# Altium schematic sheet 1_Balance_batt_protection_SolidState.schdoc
size 431 x 309 mm; Symbol: Sheet-Symbol_A3; Device: Sheet-Symbol_A3; @Project Name: BFMC_Power Board V2; @Page Count: 5; @Update Date: 2024-08-30; @Create Date: 2024-08-30; @Schematic Name: Balance_batt_protection_SolidState_4; @Page No: 1; @Page Name: Balance_batt_protection_SolidState; Company: EasyEDA.com; Reviewed: EasyEDA; Version: V0.1; Page Size: A3; Part Number: JLCPCB-001; Drawn: EasyEDA; @Board Name: greater0603 Csample-3V3config; @Create Time: 12:44:13; @Update Time: 13:32:06
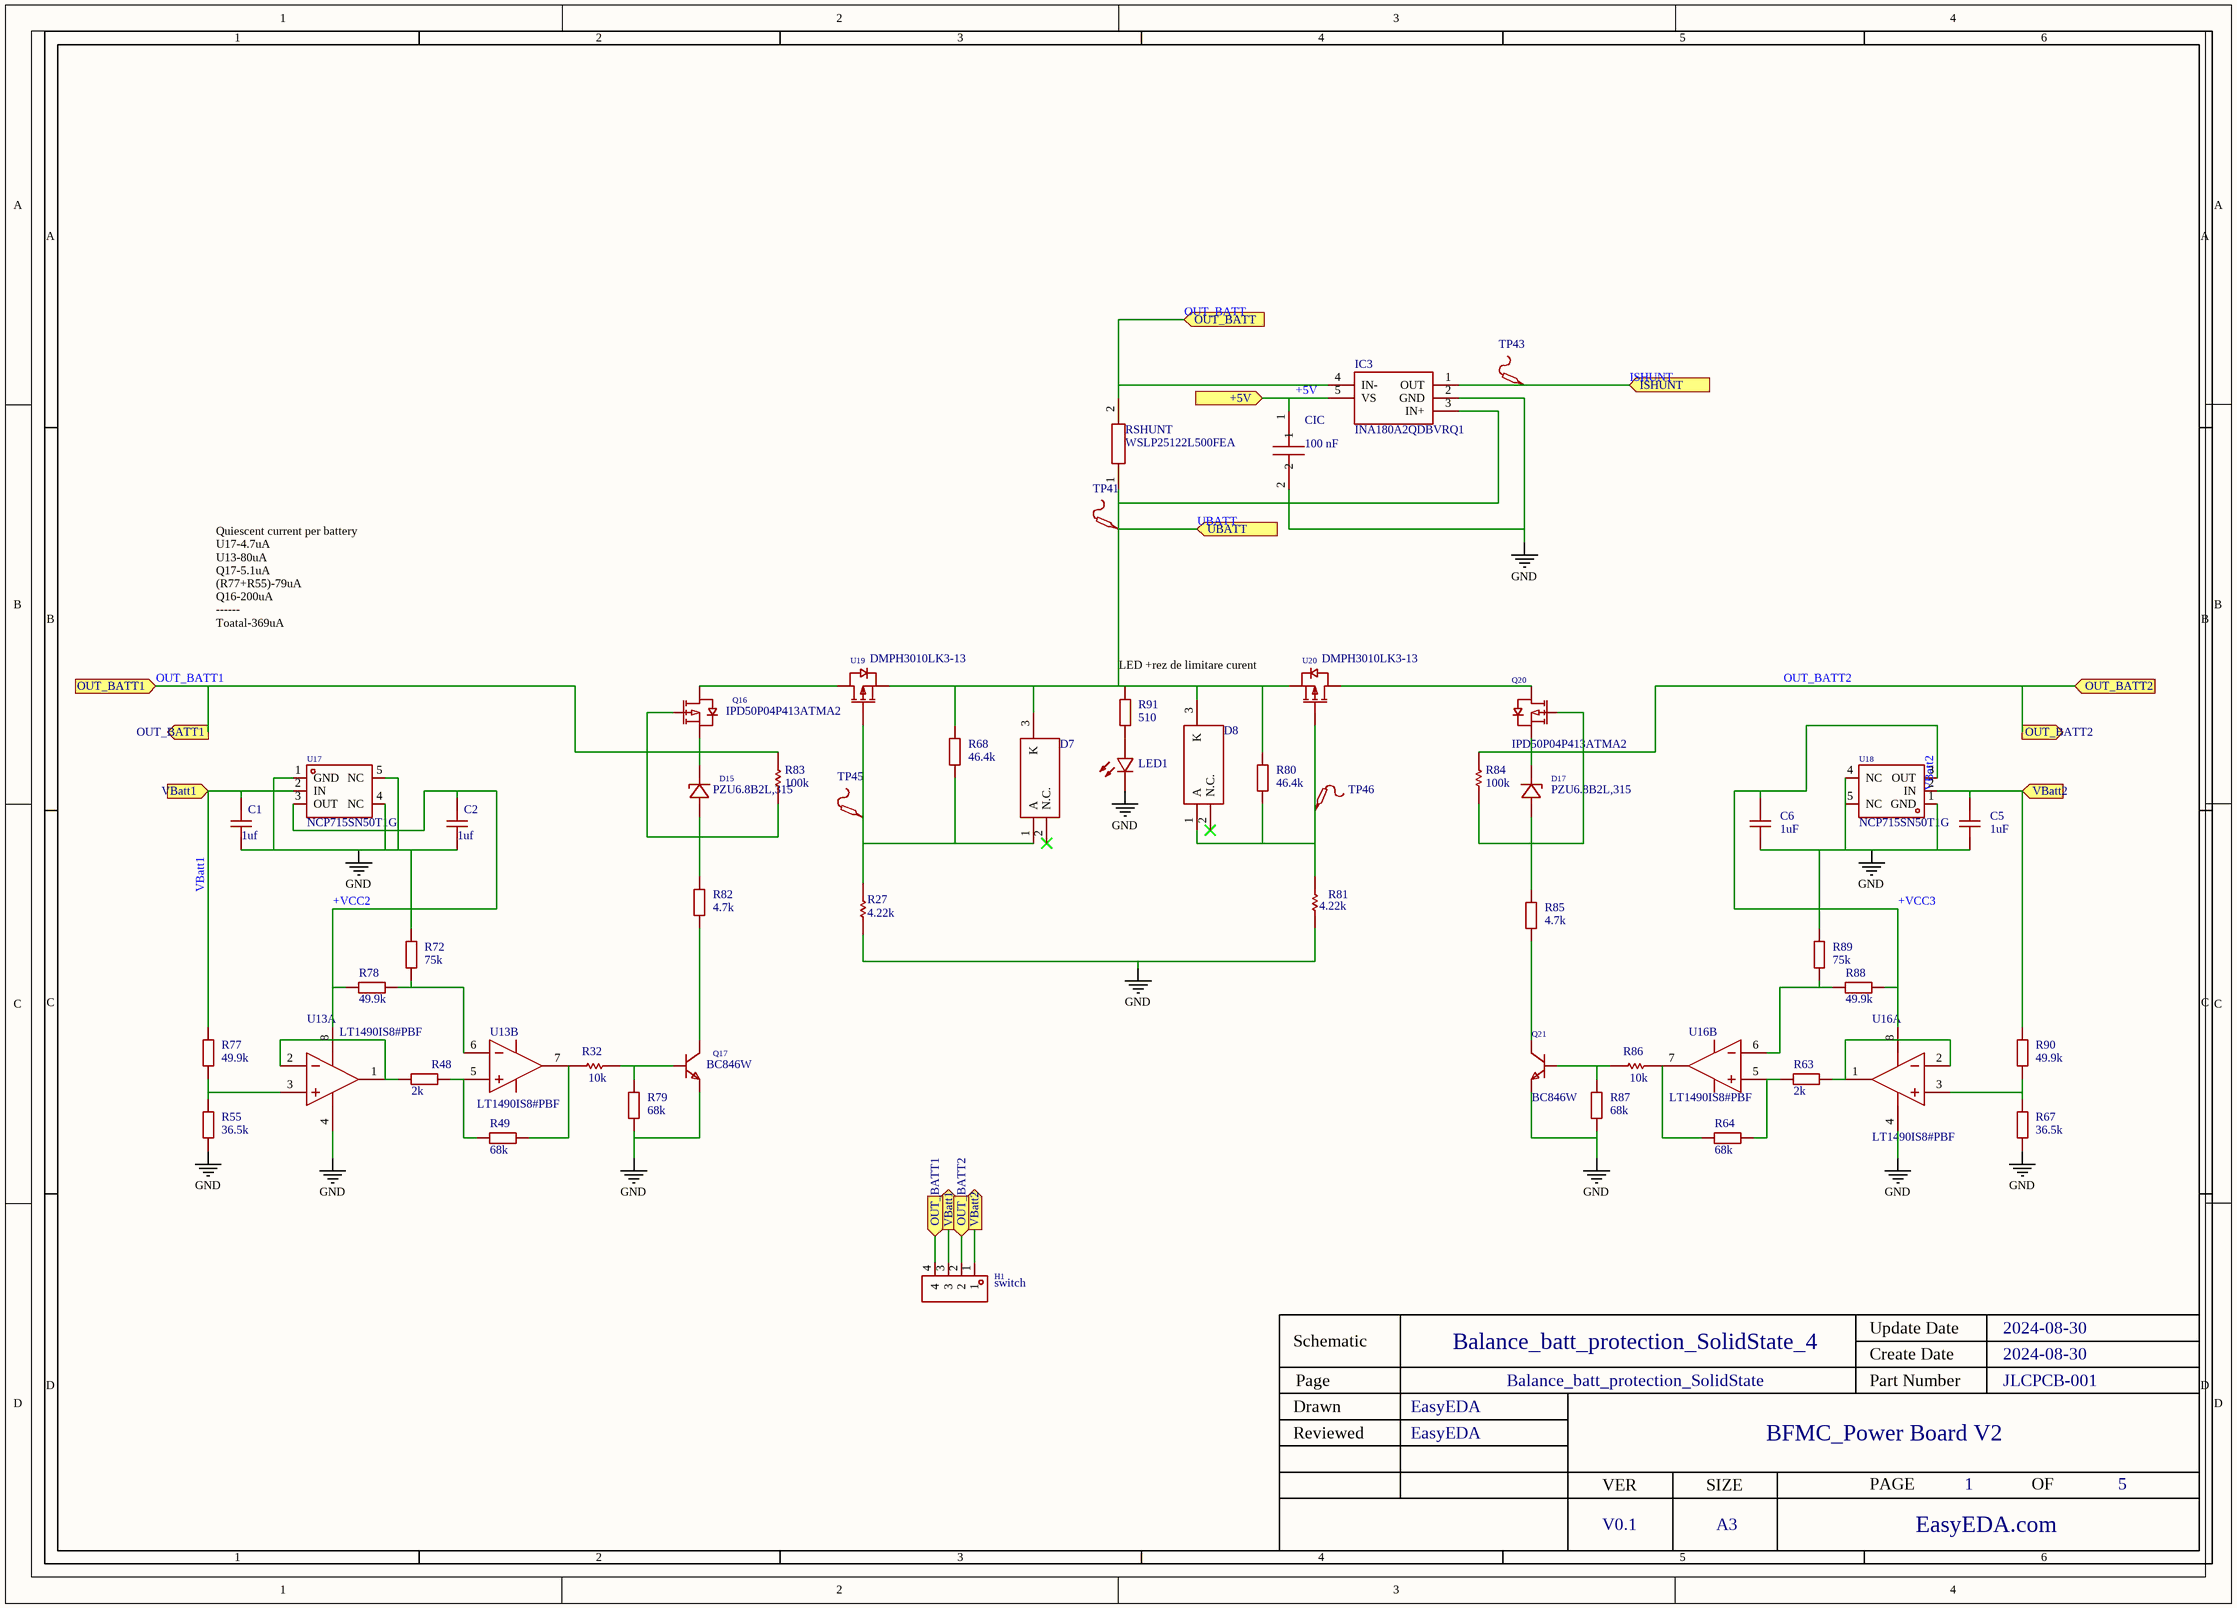
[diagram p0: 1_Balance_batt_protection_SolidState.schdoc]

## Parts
C1  1uf  [C9]  (value not drawn)
C2  1uf  [C9]  (value not drawn)
C5  1uF  [C9]  (value not drawn)
C6  1uF  [C9]  (value not drawn)
CIC  value 100 nF  [Cbst2]  (hidden comment: C2012X7S1C106K)
D7  SZBZX84C18ET1G  [SZBZX84C18ET1G]  (value not drawn)
D8  SZBZX84C18ET1G  [SZBZX84C18ET1G]  (value not drawn)
D15  PZU6.8B2L,315  [DFN1006-2L-RD]  (value not drawn)
D17  PZU6.8B2L,315  [DFN1006-2L-RD]  (value not drawn)
H1  switch  [M2021BB1W01]  (value not drawn)
IC3  INA180A2QDBVRQ1  [INA180A2QDBVRQ1]  (value not drawn)
LED1  ASCKCG00-NW5X5020302  [LEDGREEN]  (value not drawn)
Q16  IPD50P04P413ATMA2  [PG-TO252-3_L6.3-W6.5-P4.57-LS10.0-BR-CW]  (value not drawn)
Q17  BC846W  [SOT-323-3_L2.2-W1.3-P1.30-LS2.2-BR]  (value not drawn)
Q20  IPD50P04P413ATMA2  [PG-TO252-3_L6.3-W6.5-P4.57-LS10.0-BR-CW]  (value not drawn)
Q21  BC846W  [SOT-323-3_L2.2-W1.3-P1.30-LS2.2-BR]  (value not drawn)
R27  value 4.22k  [R0805_NEW]  (hidden comment: MCR03..PFX1002)
R32  value 10k  [R0603]  (hidden comment: MCR03..PFX1002)
R48  2k  [R35]  (value not drawn)
R49  68k  [R0603]  (value not drawn)
R55  36.5k  [R0603]  (value not drawn)
R63  2k  [R35]  (value not drawn)
R64  68k  [R0603]  (value not drawn)
R67  36.5k  [R0603]  (value not drawn)
R68  46.4k  [R0603]  (value not drawn)
R72  75k  [R0603]  (value not drawn)
R77  49.9k  [R0603]  (value not drawn)
R78  49.9k  [R0603]  (value not drawn)
R79  68k  [R0603]  (value not drawn)
R80  46.4k  [R0603]  (value not drawn)
R81  value 4.22k  [R0805_NEW]  (hidden comment: MCR03..PFX1002)
R82  4.7k  [R0603]  (value not drawn)
R83  value 100k  [R0805_NEW]  (hidden comment: MCR03..PFX1002)
R84  value 100k  [R0805_NEW]  (hidden comment: MCR03..PFX1002)
R85  4.7k  [R0603]  (value not drawn)
R86  value 10k  [R0603]  (hidden comment: MCR03..PFX1002)
R87  68k  [R0603]  (value not drawn)
R88  49.9k  [R0603]  (value not drawn)
R89  75k  [R0603]  (value not drawn)
R90  49.9k  [R0603]  (value not drawn)
R91  510  [R0805_NEW]  (value not drawn)
RSHUNT  WSLP25122L500FEA  [WSLP25122L000FEA BUN]  (value not drawn)
TP41  Test-Point  [Test-Point-0.5mm]  (value not drawn)
TP43  Test-Point  [Test-Point-0.5mm]  (value not drawn)
TP45  Test-Point  [Test-Point-0.5mm]  (value not drawn)
TP46  Test-Point  [Test-Point-0.5mm]  (value not drawn)
U13  LT1490IS8#PBF  [SO-8_L4.9-W3.9-P1.27-LS5.9-BL]  (value not drawn)  (parts A,B of 2)
U16  LT1490IS8#PBF  [SO-8_L4.9-W3.9-P1.27-LS5.9-BL]  (value not drawn)  (parts A,B of 2)
U17  NCP715SN50T1G  [TSOP-5_L3.0-W1.5-P0.95-BL]  (value not drawn)
U18  NCP715SN50T1G  [TSOP-5_L3.0-W1.5-P0.95-BL]  (value not drawn)
U19  DMPH3010LK3-13  [PG-TO252-3_L6.3-W6.5-P4.57-LS10.0-BR-CW]  (value not drawn)
U20  DMPH3010LK3-13  [PG-TO252-3_L6.3-W6.5-P4.57-LS10.0-BR-CW]  (value not drawn)

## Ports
+5V (in), ISHUNT (in), OUT_BATT1 (in), OUT_BATT1 (out), OUT_BATT2 (in), OUT_BATT2 (out), OUT_BATT (in), UBATT (in), VBatt1 (in), VBatt1 (out), VBatt2 (in), VBatt2 (out)

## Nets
GND: C1.2 C2.2 C5.2 C6.2 CIC.2 IC3.2(GND) LED1.1(C) Q17.2(E) Q21.2(E) R27.2 R55.1 R67.1 R72.2 R79.1 R81.2 R87.1 R89.2 U13.4(V-) U16.4(V-) U17.1(GND) U17.4(NC) U17.5(NC) U18.1(GND) U18.4(NC) U18.5(NC)
+5V: CIC.1 IC3.5(VS) ; port +5V
+VCC2: C2.1 R78.2 U13.8(V+) U17.3(OUT)
+VCC3: C6.1 R88.1 U16.8(V+) U18.3(OUT)
ISHUNT: IC3.1(OUT) TP43.1 ; port ISHUNT
OUT_BATT: IC3.4(IN-) RSHUNT.2 ; port OUT_BATT
OUT_BATT1: D15.1(C) H1.4 Q16.3(S) R83.2 ; port OUT_BATT1
OUT_BATT2: D17.1(C) H1.2 Q20.3(S) R84.2 ; port OUT_BATT2
UBATT: D7.3(K) D8.3(K) IC3.3(IN+) R68.2 R80.2 R91.2 RSHUNT.1 TP41.1 U19.3(S) U20.3(S) ; port UBATT
VBatt1: C1.1 H1.3 R77.2 U17.2(IN) ; port VBatt1
VBatt2: C5.1 H1.1 R90.1 U18.2(IN) ; port VBatt2
NetD7_1: D7.1(A) R27.1 R68.1 TP45.1 U19.1(G)
NetD8_1: D8.1(A) R80.1 R81.1 TP46.1 U20.1(G)
NetD15_2: D15.2(A) Q16.1(G) R82.2 R83.1
NetD17_2: D17.2(A) Q20.1(G) R84.1 R85.2
NetLED1_2: LED1.2(A) R91.1
NetQ16_2: Q16.2(D) U19.2(D)
NetQ17_1: Q17.1(B) R32.2 R79.2
NetQ17_3: Q17.3(C) R82.1
NetQ20_2: Q20.2(D) U20.2(D)
NetQ21_1: Q21.1(B) R86.1 R87.2
NetQ21_3: Q21.3(C) R85.1
NetR32_1: R32.1 R49.2 U13.7(OUT_B)
NetR48_1: R48.1 U13.1(OUT) U13.2(-IN)
NetR48_2: R48.2 R49.1 U13.5(+IN_B)
NetR55_2: R55.2 R77.1 U13.3(+IN)
NetR63_1: R63.1 U16.1(OUT) U16.2(-IN)
NetR63_2: R63.2 R64.1 U16.5(+IN_B)
NetR64_2: R64.2 R86.2 U16.7(OUT_B)
NetR67_2: R67.2 R90.2 U16.3(+IN)
NetR72_1: R72.1 R78.1 U13.6(-IN_B)
NetR88_2: R88.2 R89.1 U16.6(-IN_B)

Not connected (* = marked no-connect by the designer): D7 2(N.C.)*; D8 2(N.C.)*

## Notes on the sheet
- Quiescent current per battery
  U17-4.7uA
  U13-80uA
  Q17-5.1uA
  (R77+R55)-79uA
  Q16-200uA
  ------
  Toatal-369uA
- LED +rez de limitare curent

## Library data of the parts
C1 C2 C5 C6 = CAP_0201: Symbol: CAP; Convert to PCB: yes
CIC = C2012X7S1C106K: C3216X6S1V106K16; Manufacturer Part Number: C3216X6S1V106K160AC; Manufacturer Name: TDK; Symbol: Cin; Add into BOM: yes; Origin Footprint: CAPC1005X55N
D7 D8 = SZBZX84C18ET1G: Zener Diode; Manufacturer_Name: Nexperia; Symbol: BZX84W-C15F; Origin Footprint 2: SOT65P210X110-3N; Add into BOM: yes; Origin Footprint 1: SOT95P230X110-3N
D15 D17 = PZU6.8B2L,315: Diode Configuration:Single Zener Voltage (Nom):6.8V Reverse Leakage Current (Ir):500nA@3.5V Zener Voltage (Range):6.65V~6.93V Zener Voltage (Range):6.65V~6.93V Power Dissipation:250mW Zener Impedance (Zzt):20Ω Tolerance:±2% Tolerance:±2%; Manufacturer: Nexperia(安世); Add into BOM: yes; Diode Configuration: Single; Zener Voltage (Nom): 6.8V; Power Dissipation: 250mW; Zener Impedance (Zzt): 20Ω; Tolerance: ±2%
H1 = HDR-F_2.54_1x4P: Manufacturer: BOOMELE(博穆精密); Symbol: 2.54-1*4P母; Convert to PCB: yes
IC3 = INA180A2QDBVRQ1: Attenuator or Isolator; Manufacturer_Name: Texas Instruments; Origin Footprint 2: SOT95P280X145-5N; Add into BOM: yes
LED1 = 19-213/Y2C-CQ2R2L/3T(CY): Emitted Color:Yellow Power Dissipation:60mW Forward Current:20mA Dominant Wavelength:585.5nm~591.5nm Dominant Wavelength:585.5nm~591.5nm Peak Wavelength:591nm Diode Configuration:- Lens Color:无色透明透镜 Color Temperature:- Color Temperature:- Viewing Angle:12; Manufacturer: EVERLIGHT(亿光); Add into BOM: yes; Emitted Color: Yellow; Power Dissipation: 60mW; Forward Current: 20mA; Peak Wavelength: 591nm; Lens Color: 无色透明透镜; Viewing Angle: 120°
Q16 Q20 = IPD50P04P4-13: Type: Drain Source Voltage (Vdss):- Continuous Drain Current (Id):- Power Dissipation (Pd):- Drain Source On Resistance (RDS(on)@Vgs,Id):- Gate Threshold Voltage (Vgs(th)@Id):- Total Gate Charge (Qg@Vgs):- Input Capacitance (Ciss@Vds):- Reverse Transfer C; Manufacturer: Infineon(英飞凌); Add into BOM: yes
Q17 Q21 = BC846W: Manufacturer: CJ(江苏长电/长晶); Symbol: BC846W_C2885597; Add into BOM: yes
R27 R81 = MCR03..PFX1002: Resistor; Symbol: Res1; Origin Footprint 2: AXIAL-0.3; Add into BOM: yes; Origin Footprint 1: ERJP06D1000V
R32 R83 R84 R86 = MCR03..PFX1002: Resistor; Symbol: Res1; Origin Footprint 2: AXIAL-0.3; Add into BOM: yes; Origin Footprint 1: RESC1608X55N
R48 R49 R55 R63 R64 R67 R68 R72 R77-R80 R82 R85 R87-R91 = Res_0603: Symbol: Res; Convert to PCB: yes
RSHUNT = WSLP25122L500FEA: Resistor; Manufacturer_Name: Vishay; Origin Footprint 2: RESC6432X89N; Add into BOM: yes
TP41 TP43 TP45 TP46 = Test-Point: Test Point 测试点; Add into BOM: yes
U13 U16 = LT1490IS8#PBF: Number of Circuits:双路 Gain Bandwidth Product(GBP):200kHz Current - Input Bias(Ib):4nA Slew Rate(SR):0.07V/us Output Current:25mA -3db Bandwidth:- Output Type:- Rail to Rail:- Operating Temperature:-40℃~+85℃ Operating Temperature:-40℃~+85℃; Manufacturer: ADI(亚德诺); Add into BOM: yes; Number of Circuits: 双路; Gain Bandwidth Product(GBP): 200kHz; Current - Input Bias(Ib): 4nA; Output Current: 25mA
U17 U18 = NCP715SN50T1G: Manufacturer: onsemi(安森美); Add into BOM: yes
U19 U20 = DMPH3010LK3-13: Drain Source Voltage (Vdss): Drain Source On Resistance (RDS(on)@Vgs,Id):7.5mΩ Input Capacitance (Ciss@Vds):6807pF@15V; Manufacturer: DIODES(美台); Add into BOM: yes; Drain Source On Resistance (RDS(on)@Vgs,Id): 7.5mΩ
